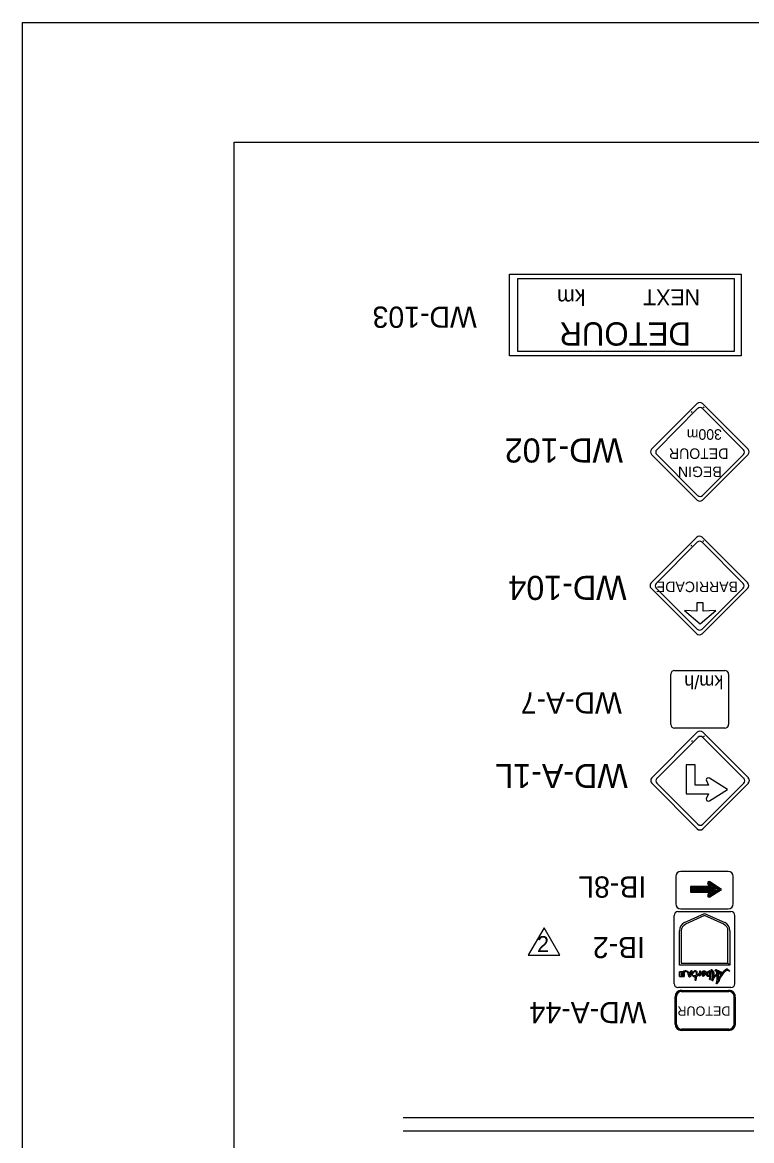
# Model space of a CAD drawing. Extents: x 1806 to 2022, y 110 to 389.
# Drawn here: x 1805.6 to 1871.5, y 288.2 to 389.2 of the extents above; entities that cross this region are included whole.
import ezdxf

# ---------------------------------------------------------------- set-up
doc = ezdxf.new("R2010")
doc.units = 0
for name, color, linetype in [('Level 10', 7, 'Continuous'), ('Level 2', 7, 'Continuous'), ('Level 44', 7, 'Continuous'), ('Level 50', 7, 'Continuous'), ('Level 53', 7, 'Continuous'), ('Level 60', 7, 'Continuous')]:
    doc.layers.add(name, color=color, linetype=linetype)

msp = doc.modelspace()

# ---------------------------------------------------------------- linework, layer by layer
at = {"layer": 'Level 10'}
for p, q in [((1871.67, 290.24), (1839.99, 290.24)), ((1871.67, 289.04), (1839.99, 289.04))]:
    msp.add_line(p, q, dxfattribs=at)
for points in [[(1870.53, 359.06), (1849.58, 359.06), (1849.58, 366.43), (1870.53, 366.43)], [(1869.88, 359.45), (1850.36, 359.45), (1850.36, 366.04), (1869.88, 366.04)]]:
    msp.add_lwpolyline(points, close=True, dxfattribs=at)
at = {"layer": 'Level 2'}
for p, q in [((1866.02, 353.94), (1866.1, 354.02)), ((1867.12, 354.37), (1867.19, 354.44)), ((1865.98, 341.87), (1866.06, 341.95)), ((1867.08, 342.3), (1867.15, 342.37)), ((1866.04, 324.25), (1866.12, 324.33)), ((1867.13, 324.68), (1867.21, 324.75)), ((1864.47, 302.35), (1864.47, 308.51)), ((1869.6, 308.85), (1864.81, 308.85)), ((1865.41, 307.87), (1867.22, 308.7)), ((1867.22, 308.51), (1865.48, 307.72)), ((1867.22, 308.7), (1869.04, 307.87)), ((1868.96, 307.72), (1867.22, 308.51)), ((1869.95, 302.35), (1869.95, 308.51)), ((1864.94, 304.02), (1864.94, 307.14)), ((1865.11, 307.14), (1865.11, 304.19)), ((1869.33, 304.19), (1869.33, 307.14)), ((1869.5, 307.14), (1869.5, 304.02)), ((1865.11, 304.19), (1869.33, 304.19)), ((1869.5, 304.02), (1869.33, 304.19)), ((1869.33, 304.19), (1869.5, 304.02)), ((1869.5, 304.02), (1864.94, 304.02)), ((1869.6, 302), (1864.81, 302)), ((1869.6, 302), (1864.81, 302))]:
    msp.add_line(p, q, dxfattribs=at)
for centre, radius, start, end in [((1864.81, 308.51), 0.347, 90, 180), ((1869.6, 308.51), 0.347, 360, 90), ((1865.74, 307.14), 0.799, 114.4568, 180), ((1865.74, 307.14), 0.628, 114.4568, 180), ((1868.7, 307.14), 0.628, 360, 65.5432), ((1868.7, 307.14), 0.799, 360, 65.5432), ((1864.81, 302.35), 0.347, 180, 270), ((1869.6, 302.35), 0.347, 270, 360)]:
    msp.add_arc(centre, radius, start, end, dxfattribs=at)
at = {"layer": 'Level 44'}
for p, q in [((1866.54, 354.75), (1862.43, 350.63)), ((1871.15, 350.63), (1867.03, 354.75)), ((1862.89, 350.58), (1866.59, 354.29)), ((1867.03, 354.29), (1870.74, 350.58)), ((1871.14, 350.63), (1871.15, 350.63)), ((1862.43, 350.14), (1866.54, 346.03)), ((1866.59, 346.44), (1862.89, 350.14)), ((1867.03, 346.03), (1871.15, 350.14)), ((1870.74, 350.14), (1867.03, 346.44)), ((1866.5, 342.68), (1862.39, 338.56)), ((1871.11, 338.56), (1866.99, 342.68)), ((1862.85, 338.51), (1866.55, 342.22)), ((1866.99, 342.22), (1870.7, 338.51)), ((1871.11, 338.56), (1871.11, 338.56)), ((1862.39, 338.07), (1866.5, 333.96)), ((1866.55, 334.37), (1862.85, 338.07)), ((1866.99, 333.96), (1871.11, 338.07)), ((1870.7, 338.07), (1866.99, 334.37)), ((1867.09, 336.74), (1866.53, 336.74)), ((1866.53, 336.74), (1866.53, 335.99)), ((1867.09, 335.99), (1867.09, 336.74)), ((1866.53, 335.99), (1865.39, 336.05)), ((1865.39, 336.05), (1866.81, 334.86)), ((1866.81, 334.86), (1868.22, 336.05)), ((1868.22, 336.05), (1867.09, 335.99)), ((1864.16, 325.77), (1864.16, 330.3)), ((1864.51, 330.65), (1869.04, 330.65)), ((1869.39, 330.65), (1869.39, 330.65)), ((1869.39, 330.3), (1869.39, 325.77)), ((1869.39, 330.3), (1869.39, 330.3)), ((1869.04, 325.42), (1864.51, 325.42)), ((1866.56, 325.06), (1862.45, 320.94)), ((1862.9, 320.89), (1866.61, 324.6)), ((1871.17, 320.94), (1867.05, 325.06)), ((1867.05, 324.6), (1870.75, 320.89)), ((1865.56, 322.13), (1865.56, 319.5)), ((1866.35, 322.13), (1865.56, 322.13)), ((1866.35, 320.29), (1866.35, 322.13)), ((1862.45, 320.45), (1866.56, 316.34)), ((1866.61, 316.75), (1862.9, 320.45)), ((1867.57, 320.29), (1866.35, 320.29)), ((1867.05, 316.34), (1871.17, 320.45)), ((1870.75, 320.45), (1867.05, 316.75)), ((1867.37, 320.75), (1867.57, 320.29)), ((1869.28, 319.9), (1867.67, 320.92)), ((1871.16, 320.94), (1871.17, 320.94)), ((1865.56, 319.5), (1867.57, 319.5)), ((1867.57, 319.5), (1867.36, 319.04)), ((1867.67, 318.87), (1869.28, 319.9)), ((1869.36, 312.49), (1865.07, 312.49)), ((1864.61, 312.03), (1864.61, 309.56)), ((1867.6, 311.14), (1865.93, 311.14)), ((1865.93, 311.14), (1865.93, 310.61)), ((1867.48, 311.45), (1867.6, 311.14)), ((1868.75, 310.87), (1867.68, 311.56)), ((1869.81, 309.56), (1869.81, 312.03)), ((1865.93, 310.61), (1867.6, 310.61)), ((1867.6, 310.61), (1867.47, 310.3)), ((1867.68, 310.19), (1868.75, 310.87)), ((1865.07, 309.11), (1869.36, 309.11)), ((1864.56, 298.71), (1864.56, 301.17)), ((1864.62, 298.71), (1864.62, 301.17)), ((1864.67, 298.71), (1864.67, 301.17)), ((1865.13, 301.75), (1869.42, 301.75)), ((1865.13, 301.69), (1869.42, 301.69)), ((1865.13, 301.64), (1869.42, 301.64)), ((1865.13, 301.64), (1865.13, 301.64)), ((1865.15, 301.59), (1865.15, 301.59)), ((1865.18, 301.53), (1865.18, 301.53)), ((1867.05, 301.64), (1867.05, 301.64)), ((1869.87, 301.17), (1869.87, 298.71)), ((1869.93, 301.17), (1869.93, 298.71)), ((1869.99, 301.17), (1869.99, 298.71)), ((1869.42, 298.25), (1865.13, 298.25)), ((1869.42, 298.2), (1865.13, 298.2)), ((1869.42, 298.13), (1865.13, 298.13))]:
    msp.add_line(p, q, dxfattribs=at)
for points in [[(1865.86, 312.5), (1865.93, 312.5)], [(1866.02, 310.69), (1867.73, 310.69), (1867.56, 310.29), (1867.61, 310.25), (1868.59, 310.87), (1867.6, 311.5), (1867.56, 311.48), (1867.73, 311.05), (1866.01, 311.05), (1866.02, 310.69), (1866.1, 310.78), (1867.86, 310.78), (1867.71, 310.41), (1868.43, 310.87), (1867.71, 311.33), (1867.86, 310.96), (1866.1, 310.96), (1866.1, 310.78), (1866.19, 310.86), (1868, 310.86), (1867.9, 310.63), (1868.27, 310.87), (1867.89, 311.11), (1867.95, 310.98), (1868.12, 310.87), (1867.96, 310.76), (1867.99, 310.87), (1867.95, 310.98), (1867.86, 310.92), (1866.19, 310.87), (1866.19, 310.86)], [(1866.02, 310.69), (1867.73, 310.69)]]:
    msp.add_lwpolyline(points, dxfattribs=at)
for centre, radius, start, end in [((1866.79, 354.5), 0.345, 45, 135), ((1866.81, 354.07), 0.31, 45, 135), ((1862.67, 350.39), 0.345, 135, 225), ((1863.11, 350.36), 0.31, 135, 225), ((1870.51, 350.36), 0.31, 315, 45), ((1870.9, 350.39), 0.345, 315, 45), ((1866.79, 346.27), 0.345, 225, 315), ((1866.81, 346.66), 0.31, 225, 315), ((1866.75, 342.43), 0.345, 45, 135), ((1866.77, 342), 0.31, 45, 135), ((1862.63, 338.31), 0.345, 135, 225), ((1863.07, 338.29), 0.31, 135, 225), ((1870.48, 338.29), 0.31, 315, 45), ((1870.86, 338.31), 0.345, 315, 45), ((1866.77, 334.59), 0.31, 225, 315), ((1866.75, 334.2), 0.345, 225, 315), ((1864.51, 330.3), 0.349, 90, 180), ((1869.04, 330.3), 0.349, 360, 90), ((1864.51, 325.77), 0.349, 180, 270), ((1869.04, 325.77), 0.349, 270, 360), ((1866.8, 324.81), 0.345, 45, 135), ((1866.83, 324.38), 0.31, 45, 135), ((1862.69, 320.7), 0.345, 135, 225), ((1863.12, 320.68), 0.31, 135, 225), ((1867.57, 320.75), 0.198, 57.5014, 179.8949), ((1870.53, 320.68), 0.31, 315, 45), ((1870.92, 320.7), 0.345, 315, 45), ((1867.56, 319.04), 0.198, 179.8942, 302.4962), ((1866.8, 316.58), 0.345, 225, 315), ((1866.83, 316.97), 0.31, 225, 315), ((1865.07, 312.03), 0.462, 90, 180), ((1869.35, 312.03), 0.462, 0, 90), ((1867.61, 311.45), 0.132, 57.5015, 179.8949), ((1867.61, 310.3), 0.132, 179.8942, 302.4962), ((1865.07, 309.56), 0.462, 180, 270), ((1869.35, 309.56), 0.462, 270, 0), ((1865.13, 301.18), 0.581, 90, 180), ((1865.13, 301.18), 0.516, 90, 180), ((1865.13, 301.18), 0.462, 90, 180), ((1869.42, 301.18), 0.581, 0, 90), ((1869.42, 301.18), 0.516, 0, 90), ((1869.42, 301.18), 0.462, 0, 90), ((1865.13, 298.71), 0.581, 180, 270), ((1865.13, 298.71), 0.516, 180, 270), ((1865.13, 298.71), 0.462, 180, 270), ((1869.42, 298.71), 0.581, 270, 360), ((1869.42, 298.71), 0.516, 270, 360), ((1869.42, 298.71), 0.462, 270, 360)]:
    msp.add_arc(centre, radius, start, end, dxfattribs=at)
at = {"layer": 'Level 53'}
msp.add_line((1865.26, 303.42), (1865.36, 303.42), dxfattribs=at)
msp.add_lwpolyline([(1865.26, 303.42), (1864.96, 303.42), (1864.96, 303.01), (1865.37, 303.01), (1865.37, 303.42), (1865.36, 303.42)], dxfattribs=at)
for points, degree in [([(1865.37, 303.01), (1865.37, 303.01), (1865.37, 303.42), (1865.37, 303.42), (1865.37, 303.42), (1865.36, 303.42), (1865.36, 303.42), (1865.27, 303.37), (1865.21, 303.27), (1865.21, 303.18), (1865.21, 303.11), (1865.25, 303.12), (1865.24, 303.11), (1865.23, 303.08), (1865.14, 303.09), (1865.14, 303.19), (1865.13, 303.28), (1865.18, 303.36), (1865.26, 303.42), (1865.26, 303.42), (1864.96, 303.42), (1864.96, 303.42), (1864.96, 303.42), (1864.96, 303.01), (1864.96, 303.01), (1864.96, 303.01), (1865.37, 303.01), (1865.37, 303.01)], 3), ([(1865.36, 303.42), (1865.27, 303.37), (1865.21, 303.27), (1865.21, 303.18), (1865.21, 303.11), (1865.25, 303.12), (1865.24, 303.11), (1865.23, 303.08), (1865.14, 303.09), (1865.14, 303.19), (1865.13, 303.28), (1865.18, 303.36), (1865.26, 303.42)], 3), ([(1865.8, 303.27), (1865.79, 303.35), (1865.74, 303.5), (1865.51, 303.5), (1865.41, 303.5), (1865.32, 303.47), (1865.26, 303.42)], 3), ([(1865.36, 303.42), (1865.4, 303.44), (1865.44, 303.46), (1865.48, 303.46)], 2), ([(1865.48, 303.46), (1865.65, 303.46), (1865.69, 303.33), (1865.7, 303.26), (1865.71, 303.22), (1865.7, 303.16), (1865.77, 303.17), (1865.82, 303.17), (1865.87, 303.27), (1865.94, 303.36), (1865.99, 303.43), (1866.02, 303.42), (1866.01, 303.36), (1865.99, 303.28), (1865.92, 303.1), (1865.85, 303.09), (1865.81, 303.08), (1865.8, 303.14), (1865.79, 303.1), (1865.77, 303.06), (1865.78, 302.98), (1865.86, 302.98), (1865.92, 302.98), (1865.98, 303.04), (1866.03, 303.11), (1866.08, 303.16), (1866.32, 303.51), (1866.41, 303.43), (1866.46, 303.4), (1866.46, 303.26), (1866.43, 303.09)], 3), ([(1866.05, 303.22), (1866.1, 303.34), (1866.13, 303.49), (1866.05, 303.51), (1865.96, 303.54), (1865.89, 303.38), (1865.8, 303.27)], 3), ([(1866.53, 303.14), (1866.55, 303.3), (1866.54, 303.44), (1866.47, 303.48), (1866.34, 303.57), (1866.15, 303.35), (1866.05, 303.22)], 3), ([(1866.43, 303.09), (1866.31, 303.04), (1866.21, 303.06), (1866.16, 303.08), (1866.13, 303.1), (1866.13, 303.1), (1866.14, 303.07), (1866.16, 303.02), (1866.25, 302.95), (1866.4, 302.99), (1866.4, 302.99), (1866.4, 302.99), (1866.41, 302.99)], 3), ([(1866.41, 302.99), (1866.4, 302.93), (1866.38, 302.88), (1866.37, 302.82), (1866.35, 302.78), (1866.31, 302.69), (1866.42, 302.67), (1866.45, 302.67), (1866.44, 302.68), (1866.45, 302.73), (1866.47, 302.81), (1866.49, 302.92), (1866.51, 303.03)], 3), ([(1866.51, 303.03), (1866.6, 303.08), (1866.68, 303.16), (1866.74, 303.27)], 2), ([(1866.81, 303.19), (1866.82, 303.29), (1866.89, 303.51), (1866.78, 303.49), (1866.74, 303.49), (1866.75, 303.48), (1866.75, 303.45), (1866.74, 303.32), (1866.64, 303.21), (1866.53, 303.14)], 3), ([(1866.74, 303.27), (1866.73, 303.22), (1866.71, 303.17), (1866.71, 303.13), (1866.71, 303.09), (1866.74, 303.08), (1866.75, 303.08), (1866.77, 303.07), (1866.8, 303.08), (1866.83, 303.12), (1866.89, 303.21), (1866.97, 303.36), (1867.1, 303.42), (1867.19, 303.46), (1867.23, 303.42), (1867.23, 303.35)], 3), ([(1867.32, 303.37), (1867.31, 303.44), (1867.27, 303.5), (1867.16, 303.49), (1867, 303.47), (1866.87, 303.28), (1866.81, 303.19)], 3), ([(1867.23, 303.35), (1867.21, 303.34), (1867.19, 303.34), (1867.18, 303.33), (1867.02, 303.26), (1866.96, 303.15), (1867.01, 303.09), (1867.04, 303.03), (1867.16, 303.04), (1867.24, 303.14), (1867.29, 303.18), (1867.32, 303.26), (1867.32, 303.33)], 3), ([(1867.14, 303.14), (1867.09, 303.09), (1867.06, 303.1), (1867.05, 303.11), (1867.04, 303.14), (1867.1, 303.24), (1867.22, 303.3)], 3), ([(1867.22, 303.3), (1867.21, 303.24), (1867.18, 303.18), (1867.14, 303.14)], 2), ([(1867.48, 303.4), (1867.43, 303.39), (1867.37, 303.38), (1867.32, 303.37)], 2), ([(1867.32, 303.33), (1867.36, 303.34), (1867.4, 303.35), (1867.45, 303.35)], 2), ([(1867.45, 303.35), (1867.38, 303.23), (1867.38, 303.06), (1867.49, 303.04), (1867.62, 303), (1867.69, 303.13), (1867.71, 303.23)], 3), ([(1867.78, 303.39), (1867.83, 303.4), (1867.85, 303.44), (1867.79, 303.47), (1867.75, 303.5), (1867.66, 303.51), (1867.57, 303.46), (1867.54, 303.45), (1867.51, 303.42), (1867.48, 303.4)], 3), ([(1867.69, 303.38), (1867.67, 303.25), (1867.6, 303.06), (1867.52, 303.09), (1867.47, 303.11), (1867.49, 303.26), (1867.56, 303.37)], 3), ([(1867.56, 303.37), (1867.6, 303.37), (1867.64, 303.37), (1867.69, 303.38)], 2), ([(1867.59, 303.41), (1867.61, 303.43), (1867.64, 303.45), (1867.66, 303.46)], 2), ([(1867.69, 303.42), (1867.67, 303.42), (1867.63, 303.41), (1867.59, 303.41)], 2), ([(1867.71, 303.23), (1867.71, 303.13), (1867.69, 303), (1867.67, 302.88), (1867.66, 302.84), (1867.62, 302.75), (1867.73, 302.73), (1867.76, 302.73), (1867.76, 302.74), (1867.75, 302.79), (1867.75, 302.85), (1867.82, 303.22), (1867.78, 303.39)], 3), ([(1867.66, 303.46), (1867.68, 303.46), (1867.69, 303.46), (1867.7, 303.46)], 2), ([(1867.7, 303.46), (1867.69, 303.45), (1867.69, 303.44), (1867.69, 303.43), (1867.69, 303.43), (1867.69, 303.42), (1867.69, 303.42)], 3), ([(1867.81, 303.57), (1867.86, 303.56), (1867.91, 303.5), (1867.93, 303.4), (1867.96, 303.23), (1867.94, 303.05), (1867.89, 302.79), (1867.88, 302.75), (1867.85, 302.66), (1867.95, 302.64), (1867.99, 302.64), (1867.97, 302.66), (1867.98, 302.7), (1868.02, 302.89), (1868.18, 303.03), (1868.34, 303.13), (1868.36, 302.91), (1868.35, 302.66), (1868.31, 302.51), (1868.27, 302.38), (1868.23, 302.4), (1868.28, 302.38), (1868.34, 302.35), (1868.39, 302.39), (1868.44, 302.48), (1868.49, 302.58), (1868.71, 303.09), (1869.06, 303.44), (1869.24, 303.62), (1869.4, 303.52), (1869.43, 303.5), (1869.46, 303.47), (1869.47, 303.51), (1869.43, 303.54), (1869.29, 303.7), (1869.08, 303.61), (1869, 303.53), (1868.79, 303.32), (1868.54, 302.86), (1868.44, 302.67), (1868.45, 302.78), (1868.45, 302.96), (1868.43, 303.18), (1868.54, 303.23), (1868.64, 303.26), (1868.68, 303.27), (1868.73, 303.29), (1868.76, 303.31), (1868.77, 303.33), (1868.77, 303.35), (1868.73, 303.38), (1868.69, 303.4), (1868.6, 303.44), (1868.35, 303.56), (1868.29, 303.59), (1868.23, 303.62), (1868.21, 303.6), (1868.19, 303.57), (1868.17, 303.52), (1868.23, 303.5), (1868.28, 303.48), (1868.3, 303.41), (1868.32, 303.31), (1868.33, 303.2), (1868.2, 303.13), (1868.08, 303.02), (1868.01, 302.89), (1868.02, 303), (1868.07, 303.37), (1867.95, 303.53), (1867.93, 303.56), (1867.87, 303.6), (1867.82, 303.59), (1867.79, 303.59), (1867.78, 303.57), (1867.78, 303.57), (1867.78, 303.56), (1867.8, 303.57), (1867.81, 303.57)], 3), ([(1868.01, 302.89), (1868.02, 303), (1868.07, 303.37), (1867.95, 303.53), (1867.93, 303.56), (1867.87, 303.6), (1867.82, 303.59), (1867.79, 303.59), (1867.78, 303.57), (1867.78, 303.57), (1867.78, 303.56), (1867.8, 303.57), (1867.81, 303.57)], 3), ([(1867.81, 303.57), (1867.86, 303.56), (1867.91, 303.5), (1867.93, 303.4), (1867.96, 303.23), (1867.94, 303.05), (1867.89, 302.79), (1867.88, 302.75), (1867.85, 302.66), (1867.95, 302.64), (1867.99, 302.64), (1867.97, 302.66), (1867.98, 302.7), (1868.02, 302.89), (1868.18, 303.03), (1868.34, 303.13)], 3), ([(1868.33, 303.2), (1868.2, 303.13), (1868.08, 303.02), (1868.01, 302.89)], 2), ([(1868.43, 303.18), (1868.54, 303.23), (1868.64, 303.26), (1868.68, 303.27), (1868.73, 303.29), (1868.76, 303.31), (1868.77, 303.33), (1868.77, 303.35), (1868.73, 303.38), (1868.69, 303.4), (1868.6, 303.44), (1868.35, 303.56), (1868.29, 303.59), (1868.23, 303.62), (1868.21, 303.6), (1868.19, 303.57), (1868.17, 303.52), (1868.23, 303.5), (1868.28, 303.48)], 3), ([(1868.34, 303.13), (1868.36, 302.91), (1868.35, 302.66), (1868.31, 302.51), (1868.27, 302.38), (1868.23, 302.4), (1868.28, 302.38), (1868.34, 302.35), (1868.39, 302.39), (1868.44, 302.48), (1868.49, 302.58), (1868.71, 303.09), (1869.06, 303.44), (1869.24, 303.62), (1869.4, 303.52), (1869.43, 303.5), (1869.46, 303.47), (1869.47, 303.51), (1869.43, 303.54), (1869.29, 303.7), (1869.08, 303.61), (1869, 303.53), (1868.79, 303.32), (1868.54, 302.86), (1868.44, 302.67)], 3), ([(1868.28, 303.48), (1868.3, 303.41), (1868.32, 303.31), (1868.33, 303.2)], 2), ([(1868.43, 303.26), (1868.41, 303.34), (1868.4, 303.41), (1868.39, 303.45)], 2), ([(1868.39, 303.45), (1868.45, 303.43), (1868.53, 303.4), (1868.63, 303.35)], 2), ([(1868.63, 303.35), (1868.57, 303.33), (1868.5, 303.3), (1868.43, 303.26), (1868.41, 303.34), (1868.4, 303.41), (1868.39, 303.45), (1868.45, 303.43), (1868.53, 303.4), (1868.63, 303.35)], 3), ([(1868.63, 303.35), (1868.57, 303.33), (1868.5, 303.3), (1868.43, 303.26)], 2), ([(1868.44, 302.67), (1868.45, 302.78), (1868.45, 302.96), (1868.43, 303.18)], 2)]:
    msp.add_open_spline(points, degree=degree, dxfattribs=at)
at = {"layer": 'Level 60'}
msp.add_line((1805.59, 389.18), (1805.59, 389.18), dxfattribs=at)
for points in [[(1805.59, 389.18), (2021.59, 389.18), (2021.59, 110.18), (1805.59, 110.18)], [(1824.71, 378.37), (2011.59, 378.37), (2011.59, 120.99), (1824.71, 120.99)]]:
    msp.add_lwpolyline(points, close=True, dxfattribs=at)
for points in [[(1852.71, 307.4), (1851.31, 304.98)], [(1854.1, 304.98), (1852.71, 307.4)], [(1851.31, 304.98), (1851.29, 304.93), (1854.13, 304.93), (1854.1, 304.98)]]:
    msp.add_lwpolyline(points, dxfattribs=at)

# ---------------------------------------------------------------- texts
at = {"layer": 'Level 10'}
for s, height, p in [('km', 1.438, (1856.45, 365.08)), ('NEXT', 1.438, (1866.8, 365.07)), ('DETOUR', 2.105, (1865.98, 362.09)), ('WD-102', 2.177, (1859.84, 351.6)), ('WD-104', 2.177, (1860.17, 339.19)), ('WD-A-1L', 2.177, (1860.28, 322.2))]:
    msp.add_text(s, height=height, rotation=180, dxfattribs=at).set_placement(p)
at = {"layer": 'Level 44'}
for s, height, p in [('300m', 0.95, (1868.78, 352.43)), ('DETOUR', 0.95, (1869.36, 350.7)), ('BEGIN', 0.95, (1868.76, 349.06)), ('BARRICADE', 0.95, (1870.23, 338.67)), ('km/h', 1.218, (1868.91, 330.21)), ('km/h', 1.218, (1868.91, 330.21)), ('DETOUR', 0.848, (1869.55, 300.3))]:
    msp.add_text(s, height=height, rotation=180, dxfattribs=at).set_placement(p)
at = {"layer": 'Level 50'}
for s, p in [('WD-103', (1846.64, 363.51)), ('WD-A-7', (1859.74, 328.67)), ('IB-8L', (1861.94, 312.04)), ('IB-2', (1861.83, 306.58)), ('WD-A-44', (1861.97, 300.7))]:
    msp.add_text(s, height=1.92, rotation=180, dxfattribs=at).set_placement(p)
at = {"layer": 'Level 60'}
msp.add_text('2', height=1.45, rotation=360, dxfattribs=at).set_placement((1852.08, 305.2))

doc.saveas('drawing.dxf')
